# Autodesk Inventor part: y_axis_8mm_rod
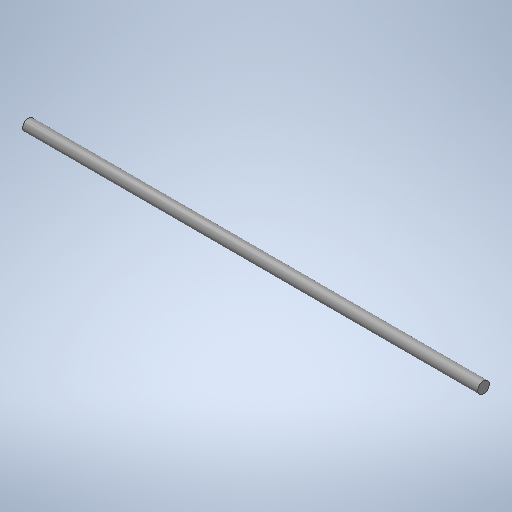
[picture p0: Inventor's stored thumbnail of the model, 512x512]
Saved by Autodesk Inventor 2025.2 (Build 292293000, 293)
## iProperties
Created: 2025-04
Part Number: y_axis_8mm_rod
Material: 1.0037 S235JR
Document SubType Name: Modeling
Designer: BennF
Density: 7.85 g/cm^3
Appearance: Stahl
Author: BennF
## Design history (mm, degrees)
sketch "Sketch2"
  geometry: C1 r 4 at (0, 0); 1 further point
  constraints: 1 centre point, 1 coincident
  dimensions: "d0" = 8 diameter of C1
extrude "Extrusion1" new body sketch "Sketch2" distance "d1" = 320; taper "d2" = 0 deg
body "Solid1"
